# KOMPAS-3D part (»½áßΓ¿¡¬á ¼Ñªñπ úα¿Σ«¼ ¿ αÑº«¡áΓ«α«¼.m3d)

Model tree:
1. Эскиз:1
2. Операция выдавливания:1
     Расстояние 1 = 6
3. Эскиз:2
4. Вырезать элемент выдавливания:1
     Толщина стенки 2 = 1.5; Расстояние 1 = 21
